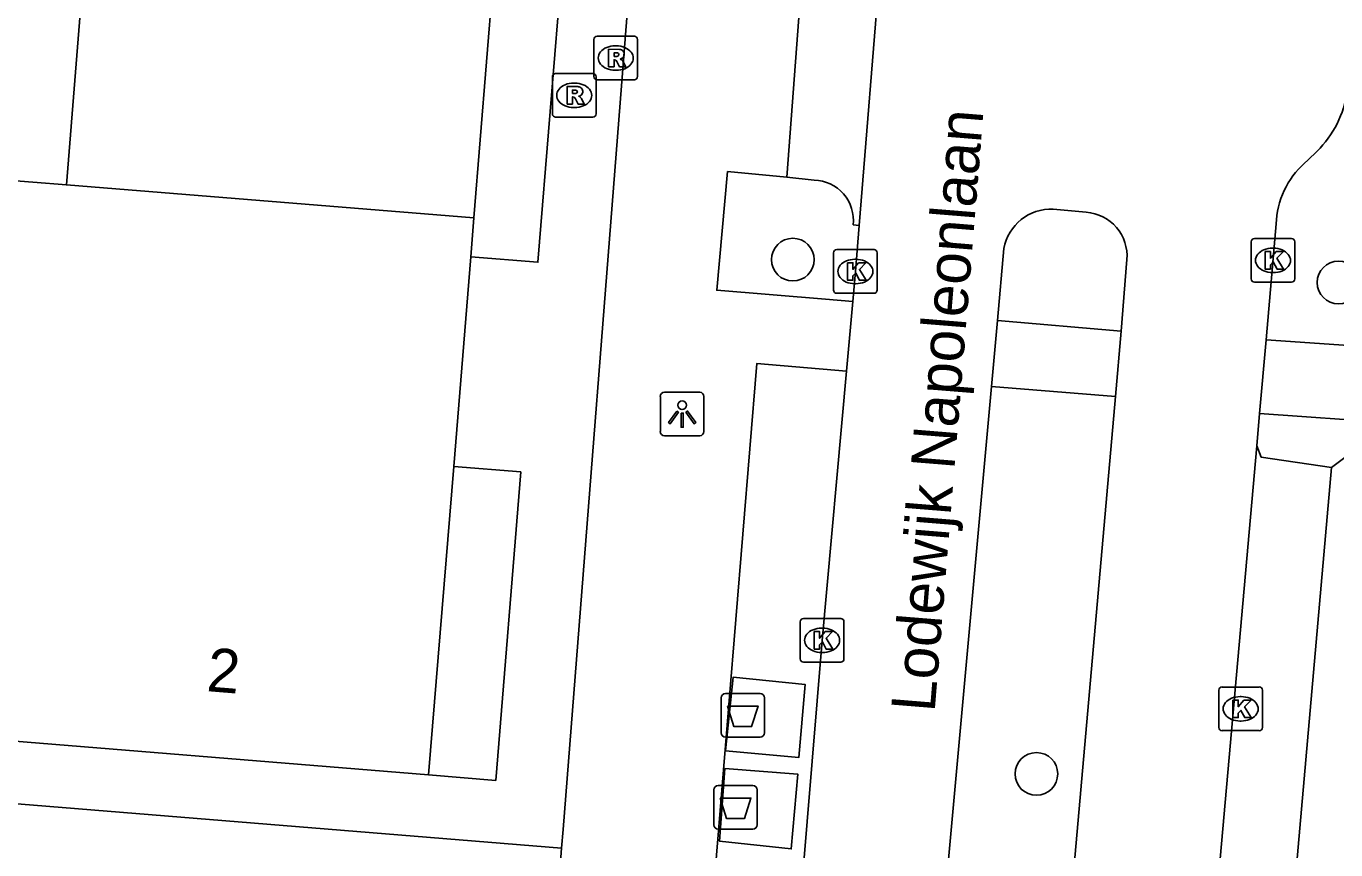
# Model space of a CAD drawing. Extents: x 159961 to 160856, y 382704 to 383353.
# Drawn here: x 160570.73 to 160600.71, y 383249.21 to 383268.08 of the extents above; entities that cross this region are included whole.
import ezdxf

# ---------------------------------------------------------------- set-up
doc = ezdxf.new("R2010")
doc.units = 0
for name, color, linetype in [('IMGEO_Afval_apart_plaats', 7, 'Continuous'), ('IMGEO_Boom', 7, 'Continuous'), ('IMGEO_Kolk', 7, 'Continuous'), ('IMGEO_Lichtpunt', 7, 'Continuous'), ('IMGEO_Openbare_ruimte_label', 7, 'Continuous'), ('IMGEO_Pand', 7, 'Continuous'), ('IMGEO_Pand_nummerreeks', 7, 'Continuous'), ('IMGEO_Pand_overbouw', 7, 'Continuous'), ('IMGEO_Parkeervlak_open', 7, 'Continuous'), ('IMGEO_Rijbaan_lokaal_open', 7, 'Continuous'), ('IMGEO_Rioolput', 7, 'Continuous'), ('IMGEO_Voetpad_gesloten', 7, 'Continuous'), ('IMGEO_Voetpad_open', 7, 'Continuous')]:
    doc.layers.add(name, color=color, linetype=linetype)

msp = doc.modelspace()

# ---------------------------------------------------------------- linework, layer by layer
at = {"layer": 'IMGEO_Afval_apart_plaats'}
for p, q in [((160586.64, 383251.892), (160586.64, 383252.692)), ((160586.64, 383252.692), (160586.64, 383251.892)), ((160586.74, 383252.792), (160587.53, 383252.792)), ((160587.53, 383252.792), (160586.74, 383252.792)), ((160587.63, 383252.692), (160587.63, 383251.892)), ((160587.63, 383251.892), (160587.63, 383252.692)), ((160587.53, 383251.792), (160586.74, 383251.792)), ((160586.74, 383251.792), (160587.53, 383251.792)), ((160586.474, 383249.785), (160586.474, 383250.585)), ((160586.474, 383250.585), (160586.474, 383249.785)), ((160586.574, 383250.685), (160587.364, 383250.685)), ((160587.364, 383250.685), (160586.574, 383250.685)), ((160587.464, 383250.585), (160587.464, 383249.785)), ((160587.464, 383249.785), (160587.464, 383250.585)), ((160587.364, 383249.685), (160586.574, 383249.685)), ((160586.574, 383249.685), (160587.364, 383249.685))]:
    msp.add_line(p, q, dxfattribs=at)
for points in [[(160586.783, 383252.506), (160587.487, 383252.506), (160587.338, 383252.036), (160586.932, 383252.036), (160586.783, 383252.506)], [(160586.617, 383250.399), (160587.321, 383250.399), (160587.172, 383249.929), (160586.766, 383249.929), (160586.617, 383250.399)]]:
    msp.add_lwpolyline(points, dxfattribs=at)
for centre, start, end in [((160586.74, 383252.692), 90, 180), ((160586.74, 383252.692), 90, 180), ((160587.53, 383252.692), 0, 90), ((160587.53, 383252.692), 360, 90), ((160586.74, 383251.892), 180, 270), ((160586.74, 383251.892), 180, 270), ((160587.53, 383251.892), 270, 0), ((160587.53, 383251.892), 270, 0), ((160586.574, 383250.585), 90, 180), ((160586.574, 383250.585), 90, 180), ((160587.364, 383250.585), 0, 90), ((160587.364, 383250.585), 360, 90), ((160586.574, 383249.785), 180, 270), ((160586.574, 383249.785), 180, 270), ((160587.364, 383249.785), 270, 0), ((160587.364, 383249.785), 270, 0)]:
    msp.add_arc(centre, 0.1, start, end, dxfattribs=at)
at = {"layer": 'IMGEO_Boom'}
for centre in [(160588.281, 383262.732), (160600.777, 383262.21), (160593.858, 383250.951)]:
    msp.add_circle(centre, 0.489, dxfattribs=at)
at = {"layer": 'IMGEO_Kolk'}
for p, q in [((160598.774, 383262.289), (160598.774, 383263.141)), ((160598.849, 383263.215), (160599.701, 383263.215)), ((160599.262, 383262.995), (160599.287, 383262.995)), ((160599.775, 383263.141), (160599.775, 383262.289)), ((160589.213, 383262.035), (160589.213, 383262.887)), ((160589.288, 383262.961), (160590.14, 383262.961)), ((160589.701, 383262.741), (160589.726, 383262.741)), ((160590.214, 383262.887), (160590.214, 383262.035)), ((160599.285, 383262.435), (160599.26, 383262.435)), ((160589.724, 383262.181), (160589.699, 383262.181)), ((160599.701, 383262.215), (160598.849, 383262.215)), ((160590.14, 383261.961), (160589.288, 383261.961)), ((160588.451, 383253.585), (160588.451, 383254.437)), ((160588.526, 383254.511), (160589.378, 383254.511)), ((160589.452, 383254.437), (160589.452, 383253.585)), ((160588.939, 383254.291), (160588.964, 383254.291)), ((160588.962, 383253.731), (160588.937, 383253.731)), ((160589.378, 383253.511), (160588.526, 383253.511)), ((160598.034, 383252.016), (160598.034, 383252.868)), ((160598.109, 383252.942), (160598.961, 383252.942)), ((160599.035, 383252.868), (160599.035, 383252.016)), ((160598.522, 383252.722), (160598.547, 383252.722)), ((160598.961, 383251.942), (160598.109, 383251.942)), ((160598.545, 383252.162), (160598.52, 383252.162))]:
    msp.add_line(p, q, dxfattribs=at)
for points in [[(160598.774, 383262.289), (160598.774, 383263.141)], [(160598.849, 383263.215), (160599.701, 383263.215)], [(160599.775, 383263.141), (160599.775, 383262.289)], [(160589.213, 383262.035), (160589.213, 383262.887)], [(160589.288, 383262.961), (160590.14, 383262.961)], [(160590.214, 383262.887), (160590.214, 383262.035)], [(160599.095, 383262.915), (160599.218, 383262.915), (160599.218, 383262.764), (160599.348, 383262.915), (160599.512, 383262.915), (160599.366, 383262.764), (160599.519, 383262.515), (160599.367, 383262.515), (160599.282, 383262.679), (160599.218, 383262.612), (160599.218, 383262.515), (160599.095, 383262.515), (160599.095, 383262.915)], [(160589.534, 383262.661), (160589.657, 383262.661), (160589.657, 383262.51), (160589.787, 383262.661), (160589.951, 383262.661), (160589.805, 383262.51), (160589.958, 383262.261), (160589.806, 383262.261), (160589.721, 383262.425), (160589.657, 383262.358), (160589.657, 383262.261), (160589.534, 383262.261), (160589.534, 383262.661)], [(160599.701, 383262.215), (160598.849, 383262.215)], [(160590.14, 383261.961), (160589.288, 383261.961)], [(160588.451, 383253.585), (160588.451, 383254.437)], [(160588.526, 383254.511), (160589.378, 383254.511)], [(160589.452, 383254.437), (160589.452, 383253.585)], [(160588.772, 383254.211), (160588.895, 383254.211), (160588.895, 383254.06), (160589.025, 383254.211), (160589.189, 383254.211), (160589.043, 383254.06), (160589.196, 383253.811), (160589.044, 383253.811), (160588.959, 383253.975), (160588.895, 383253.908), (160588.895, 383253.811), (160588.772, 383253.811), (160588.772, 383254.211)], [(160589.378, 383253.511), (160588.526, 383253.511)], [(160598.034, 383252.016), (160598.034, 383252.868)], [(160598.109, 383252.942), (160598.961, 383252.942)], [(160599.035, 383252.868), (160599.035, 383252.016)], [(160598.355, 383252.642), (160598.478, 383252.642), (160598.478, 383252.491), (160598.608, 383252.642), (160598.772, 383252.642), (160598.626, 383252.491), (160598.779, 383252.242), (160598.627, 383252.242), (160598.542, 383252.406), (160598.478, 383252.339), (160598.478, 383252.242), (160598.355, 383252.242), (160598.355, 383252.642)], [(160598.961, 383251.942), (160598.109, 383251.942)]]:
    msp.add_lwpolyline(points, dxfattribs=at)
for centre, start, end in [((160598.851, 383263.139), 91.552, 178.448), ((160598.851, 383263.139), 91.552, 178.448), ((160599.699, 383263.139), 1.552, 88.448), ((160599.699, 383263.139), 1.552, 88.448), ((160589.29, 383262.885), 91.552, 178.448), ((160589.29, 383262.885), 91.552, 178.448), ((160590.138, 383262.885), 1.552, 88.448), ((160590.138, 383262.885), 1.552, 88.448), ((160598.851, 383262.291), 181.552, 268.448), ((160598.851, 383262.291), 181.552, 268.448), ((160599.699, 383262.291), 271.552, 358.448), ((160599.699, 383262.291), 271.552, 358.448), ((160589.29, 383262.037), 181.552, 268.448), ((160589.29, 383262.037), 181.552, 268.448), ((160590.138, 383262.037), 271.552, 358.448), ((160590.138, 383262.037), 271.552, 358.448), ((160588.528, 383254.435), 91.552, 178.448), ((160588.528, 383254.435), 91.552, 178.448), ((160589.376, 383254.435), 1.552, 88.448), ((160589.376, 383254.435), 1.552, 88.448), ((160588.528, 383253.587), 181.552, 268.448), ((160588.528, 383253.587), 181.552, 268.448), ((160589.376, 383253.587), 271.552, 358.448), ((160589.376, 383253.587), 271.552, 358.448), ((160598.111, 383252.866), 91.552, 178.448), ((160598.111, 383252.866), 91.552, 178.448), ((160598.959, 383252.866), 1.552, 88.448), ((160598.959, 383252.866), 1.552, 88.448), ((160598.111, 383252.018), 181.552, 268.448), ((160598.111, 383252.018), 181.552, 268.448), ((160598.959, 383252.018), 271.552, 358.448), ((160598.959, 383252.018), 271.552, 358.448)]:
    msp.add_arc(centre, 0.0765, start, end, dxfattribs=at)
for centre, major_axis, ratio, start_param, end_param in [((160599.261, 383262.715), (-0.387, 0.002), 0.722429, 4.712389, 7.853982), ((160599.286, 383262.715), (-0.39, 0.002), 0.717154, 1.570796, 4.712389), ((160589.7, 383262.461), (-0.387, 0.002), 0.722429, 4.712389, 7.853982), ((160589.725, 383262.461), (-0.39, 0.002), 0.717154, 1.570796, 4.712389), ((160588.938, 383254.011), (-0.387, 0.002), 0.722429, 4.712389, 7.853982), ((160588.963, 383254.011), (-0.39, 0.002), 0.717154, 1.570796, 4.712389), ((160598.521, 383252.442), (-0.387, 0.002), 0.722429, 4.712389, 7.853982), ((160598.546, 383252.442), (-0.39, 0.002), 0.717154, 1.570796, 4.712389)]:
    msp.add_ellipse(centre, major_axis=major_axis, ratio=ratio, start_param=start_param, end_param=end_param, dxfattribs=at)
at = {"layer": 'IMGEO_Lichtpunt'}
for p, q in [((160586.15, 383259.695), (160585.342, 383259.695)), ((160586.15, 383259.695), (160585.342, 383259.695)), ((160585.248, 383259.6), (160585.248, 383258.793)), ((160585.248, 383259.6), (160585.248, 383258.793)), ((160586.244, 383258.793), (160586.244, 383259.6)), ((160586.244, 383258.793), (160586.244, 383259.6)), ((160585.342, 383258.699), (160586.15, 383258.699)), ((160585.342, 383258.699), (160586.15, 383258.699))]:
    msp.add_line(p, q, dxfattribs=at)
for points in [[(160585.622, 383259.264), (160585.661, 383259.236), (160585.473, 383258.974), (160585.435, 383259.001), (160585.622, 383259.264)], [(160585.724, 383259.216), (160585.771, 383259.216), (160585.771, 383258.894), (160585.724, 383258.894), (160585.724, 383259.216)], [(160585.834, 383259.236), (160585.872, 383259.263), (160586.059, 383259.001), (160586.02, 383258.973), (160585.834, 383259.236)]]:
    msp.add_lwpolyline(points, dxfattribs=at)
msp.add_circle((160585.747, 383259.398), 0.0994, dxfattribs=at)
for centre, start, end in [((160585.342, 383259.6), 90, 180), ((160585.342, 383259.6), 90, 180), ((160586.15, 383259.6), 0, 90), ((160586.15, 383259.6), 0, 90), ((160585.342, 383258.793), 180, 270), ((160585.342, 383258.793), 180, 270), ((160586.15, 383258.793), 270, 0), ((160586.15, 383258.793), 270, 360)]:
    msp.add_arc(centre, 0.0946, start, end, dxfattribs=at)
at = {"layer": 'IMGEO_Pand'}
for points in [[(160569.89, 383262.014), (160570.099, 383264.568), (160571.648, 383264.443), (160580.98, 383263.693)], [(160580.98, 383263.693), (160580.907, 383262.797), (160580.516, 383257.996), (160579.941, 383250.929), (160569.055, 383251.813)]]:
    msp.add_lwpolyline(points, dxfattribs=at)
at = {"layer": 'IMGEO_Pand_overbouw'}
for points in [[(160583.007, 383269.588), (160581.47, 383269.713), (160581.416, 383269.055), (160572.079, 383269.806), (160571.648, 383264.443), (160580.98, 383263.693), (160580.907, 383262.797), (160582.445, 383262.672)], [(160582.055, 383257.871), (160580.516, 383257.996), (160579.941, 383250.929), (160581.48, 383250.804)]]:
    msp.add_lwpolyline(points, close=True, dxfattribs=at)
at = {"layer": 'IMGEO_Parkeervlak_open'}
msp.add_lwpolyline([(160598.904, 383258.469), (160599.003, 383258.209), (160600.613, 383257.967)], dxfattribs=at)
at = {"layer": 'IMGEO_Rijbaan_lokaal_open'}
for points in [[(160590.279, 383269.46), (160589.799, 383263.517)], [(160600.075, 383265.01), (160600.285, 383265.215)], [(160594.242, 383263.889), (160594.999, 383263.817)], [(160599.116, 383260.897), (160599.356, 383263.646)], [(160589.799, 383263.517), (160589.714, 383262.461), (160589.652, 383261.774)], [(160592.965, 383261.338), (160593.115, 383262.985)], [(160595.93, 383262.735), (160595.799, 383261.097)], [(160589.508, 383260.177), (160589.652, 383261.774)], [(160592.828, 383259.826), (160592.965, 383261.338)], [(160595.799, 383261.097), (160595.667, 383259.595)], [(160598.968, 383259.204), (160599.116, 383260.897)], [(160589.508, 383260.177), (160588.952, 383254.011), (160588.498, 383248.477)], [(160591.194, 383241.85), (160592.828, 383259.826)], [(160595.667, 383259.595), (160594.082, 383241.578)], [(160598.904, 383258.469), (160598.968, 383259.204)], [(160597.806, 383246.082), (160598.904, 383258.469)]]:
    msp.add_lwpolyline(points, dxfattribs=at)
for centre, radius, start, end in [((160598.593, 383266.918), 2.401, 314.8143, 352.1223), ((160601.291, 383263.497), 1.941, 128.8016, 175.6087), ((160594.192, 383262.797), 1.093, 87.3563, 170.1119), ((160594.93, 383262.816), 1.003, 355.3501, 86.0702)]:
    msp.add_arc(centre, radius, start, end, dxfattribs=at)
at = {"layer": 'IMGEO_Rioolput'}
for p, q in [((160583.801, 383267.85), (160584.653, 383267.85)), ((160583.726, 383266.924), (160583.726, 383267.776)), ((160584.214, 383267.63), (160584.239, 383267.63)), ((160584.727, 383267.776), (160584.727, 383266.924)), ((160582.775, 383266.071), (160582.775, 383266.923)), ((160582.85, 383266.997), (160583.702, 383266.997)), ((160583.776, 383266.923), (160583.776, 383266.071)), ((160584.237, 383267.07), (160584.212, 383267.07)), ((160583.263, 383266.777), (160583.288, 383266.777)), ((160584.653, 383266.85), (160583.801, 383266.85)), ((160583.702, 383265.997), (160582.85, 383265.997)), ((160583.286, 383266.217), (160583.261, 383266.217))]:
    msp.add_line(p, q, dxfattribs=at)
for points in [[(160583.801, 383267.85), (160584.653, 383267.85)], [(160583.726, 383266.924), (160583.726, 383267.776)], [(160584.315, 383267.548), (160584.063, 383267.55), (160584.063, 383267.15)], [(160584.727, 383267.776), (160584.727, 383266.924)], [(160584.063, 383267.15), (160584.187, 383267.15), (160584.187, 383267.312), (160584.198, 383267.312)], [(160584.241, 383267.469), (160584.187, 383267.469), (160584.187, 383267.388)], [(160584.187, 383267.388), (160584.239, 383267.388)], [(160584.245, 383267.283), (160584.316, 383267.15), (160584.456, 383267.15), (160584.391, 383267.276)], [(160582.775, 383266.071), (160582.775, 383266.923)], [(160582.85, 383266.997), (160583.702, 383266.997)], [(160583.776, 383266.923), (160583.776, 383266.071)], [(160583.364, 383266.695), (160583.112, 383266.697), (160583.112, 383266.297)], [(160583.29, 383266.616), (160583.236, 383266.616), (160583.236, 383266.535)], [(160584.653, 383266.85), (160583.801, 383266.85)], [(160583.112, 383266.297), (160583.236, 383266.297), (160583.236, 383266.459), (160583.247, 383266.459)], [(160583.236, 383266.535), (160583.288, 383266.535)], [(160583.294, 383266.43), (160583.365, 383266.297), (160583.505, 383266.297), (160583.44, 383266.423)], [(160583.702, 383265.997), (160582.85, 383265.997)]]:
    msp.add_lwpolyline(points, dxfattribs=at)
for centre, radius, start, end in [((160583.803, 383267.774), 0.0765, 91.552, 178.448), ((160583.803, 383267.774), 0.0765, 91.552, 178.448), ((160584.651, 383267.774), 0.0765, 1.552, 88.448), ((160584.651, 383267.774), 0.0765, 1.552, 88.448), ((160584.314, 383267.438), 0.109, 350.3612, 89.416), ((160584.197, 383267.259), 0.0533, 26.0293, 88.6989), ((160584.223, 383267.577), 0.19, 274.7715, 282.9687), ((160584.247, 383267.373), 0.0964, 77.0061, 93.1865), ((160584.261, 383267.43), 0.0378, 276.6634, 79.6772), ((160584.312, 383267.438), 0.112, 277.5842, 350.9817), ((160584.296, 383267.223), 0.108, 29.5134, 73.7905), ((160582.852, 383266.921), 0.0765, 91.552, 178.448), ((160582.852, 383266.921), 0.0765, 91.552, 178.448), ((160583.7, 383266.921), 0.0765, 1.552, 88.448), ((160583.7, 383266.921), 0.0765, 1.552, 88.448), ((160583.803, 383266.926), 0.0765, 181.552, 268.448), ((160583.803, 383266.926), 0.0765, 181.552, 268.448), ((160584.651, 383266.926), 0.0765, 271.552, 358.448), ((160584.651, 383266.926), 0.0765, 271.552, 358.448), ((160583.296, 383266.52), 0.0964, 77.0061, 93.1865), ((160583.31, 383266.577), 0.0378, 276.6634, 79.6772), ((160583.363, 383266.585), 0.109, 350.3612, 89.416), ((160583.246, 383266.406), 0.0533, 26.0293, 88.6989), ((160583.272, 383266.724), 0.19, 274.7715, 282.9687), ((160583.361, 383266.585), 0.112, 277.5842, 350.9817), ((160583.345, 383266.37), 0.108, 29.5134, 73.7905), ((160582.852, 383266.073), 0.0765, 181.552, 268.448), ((160582.852, 383266.073), 0.0765, 181.552, 268.448), ((160583.7, 383266.073), 0.0765, 271.552, 358.448), ((160583.7, 383266.073), 0.0765, 271.552, 358.448)]:
    msp.add_arc(centre, radius, start, end, dxfattribs=at)
for centre, major_axis, ratio, start_param, end_param in [((160584.213, 383267.35), (-0.387, 0.002), 0.722429, 4.712389, 7.853982), ((160584.238, 383267.35), (-0.39, 0.002), 0.717154, 1.570796, 4.712389), ((160583.262, 383266.497), (-0.387, 0.002), 0.722429, 4.712389, 7.853982), ((160583.287, 383266.497), (-0.39, 0.002), 0.717154, 1.570796, 4.712389)]:
    msp.add_ellipse(centre, major_axis=major_axis, ratio=ratio, start_param=start_param, end_param=end_param, dxfattribs=at)
at = {"layer": 'IMGEO_Voetpad_gesloten'}
for points in [[(160586.741, 383251.481), (160588.42, 383251.329), (160588.566, 383252.998), (160586.912, 383253.166), (160586.741, 383251.481)], [(160586.726, 383251.078), (160586.603, 383249.409), (160588.246, 383249.232), (160588.393, 383250.947), (160586.726, 383251.078)]]:
    msp.add_lwpolyline(points, dxfattribs=at)
at = {"layer": 'IMGEO_Voetpad_open'}
for points in [[(160602.304, 383282.068), (160603.919, 383281.948), (160603.504, 383277.414), (160603.251, 383275.145), (160602.112, 383260.689), (160599.116, 383260.897)], [(160584.569, 383269.446), (160583.022, 383249.676), (160582.981, 383249.253)], [(160581.416, 383269.055), (160580.98, 383263.693)], [(160588.145, 383264.618), (160588.441, 383268.586), (160589.074, 383268.562)], [(160589.652, 383261.774), (160589.033, 383261.825), (160586.539, 383262.032), (160586.787, 383264.751), (160588.145, 383264.618)], [(160588.145, 383264.618), (160588.771, 383264.556)], [(160589.665, 383263.528), (160589.799, 383263.517)], [(160592.965, 383261.338), (160595.799, 383261.097)], [(160463.599, 383260.364), (160463.483, 383258.927), (160513.315, 383254.922), (160543.34, 383252.481), (160582.981, 383249.253)], [(160586.496, 383248.621), (160587.457, 383260.35), (160589.508, 383260.177)], [(160592.828, 383259.826), (160595.667, 383259.595)], [(160598.968, 383259.204), (160601.978, 383258.994), (160600.613, 383257.967)], [(160600.613, 383257.967), (160599.578, 383246.145)], [(160582.981, 383249.253), (160582.88, 383247.781)]]:
    msp.add_lwpolyline(points, dxfattribs=at)
msp.add_arc((160588.742, 383263.628), 0.928, 353.7919, 88.2318, dxfattribs=at)

# ---------------------------------------------------------------- texts
at = {"layer": 'IMGEO_Openbare_ruimte_label'}
msp.add_text('Lodewijk Napoleonlaan', height=1, rotation=85.3553, dxfattribs=at).set_placement((160591.527, 383252.349))
at = {"layer": 'IMGEO_Pand_nummerreeks'}
msp.add_text('2', height=1, rotation=355.3533, dxfattribs=at).set_placement((160574.842, 383252.849))

doc.saveas('drawing.dxf')
